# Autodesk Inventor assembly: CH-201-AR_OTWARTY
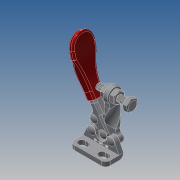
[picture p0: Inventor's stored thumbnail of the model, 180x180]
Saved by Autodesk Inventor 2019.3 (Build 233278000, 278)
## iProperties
Company: ·L?¤¤?
Created: 2010-06
Part Number: CH-201-AR_OTWARTY
Material: Ogólny
Description: STEP AP203
Document SubType Name: Assembly
Designer: CADENGINEERING4
Sending System: SolidWorks 2005179
Preprocessor: SwSTEP 2.0
Title: CH-201-AR.STEP
Author: ·L?¥Î?
Revision Number: ANY
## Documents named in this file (8)
- E:\STRONA\Horizontal toggle clamp\CH-201-AR\CH-201-AR_OTWARTY.iam
- E:\STRONA\Horizontal toggle clamp\CH-201-AR\201-AR-01___.ipt
- E:\STRONA\Horizontal toggle clamp\CH-201-AR\201-A-02___.ipt
- E:\STRONA\Horizontal toggle clamp\CH-201-AR\201-06___.ipt
- E:\STRONA\Horizontal toggle clamp\CH-201-AR\M4___.ipt
- E:\STRONA\Horizontal toggle clamp\CH-201-AR\201-03___.iam
- E:\STRONA\Horizontal toggle clamp\CH-201-AR\CH-SA-042007___.ipt
- E:\STRONA\Horizontal toggle clamp\CH-201-AR\201-A-04___.ipt
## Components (12 placed, 12 different names)
1. 201-AR-01_??_1 — Zestawiające:6, Zestawiające:7, Zestawiające:8, Zestawiające:16, Zestawiające:17, Zestawiające:20, Przejściowe:1
2. 201-A-02_??_2 — Zestawiające:1, Zestawiające:4, Zestawiające:5, Zestawiające:6, Zestawiające:22, Zestawiające:23
3. 201-06_??_3 — Zestawiające:7, Zestawiające:8, Zestawiające:22
4. 201-06_??_4 — Zestawiające:20, Zestawiające:21
5. M4_??_5 — Zestawiające:3, Zestawiające:5
6. M4_??_6 — Równoległe:1, Zestawiające:2, Zestawiające:4
7. 201-03_??_7 [sub-assembly] — Zestawiające:9, Zestawiające:10, Zestawiające:11, Zestawiające:12, Zestawiające:19, Przejściowe:1
8. 201-06_??_8 — Zestawiające:9, Zestawiające:12, Zestawiające:18
9. CH-SA-042007_??_9 — Równoległe:1, Zestawiające:1, Zestawiające:2, Zestawiające:3
10. 201-06_??_10 — Zestawiające:10, Zestawiające:11, Zestawiające:23
11. 201-A-04_??_11 — Zestawiające:13, Zestawiające:14, Zestawiające:15, Zestawiające:16, Zestawiające:18, Zestawiające:19, Zestawiające:21
12. 201-A-04_??_12 — Zestawiające:13, Zestawiające:14, Zestawiające:15, Zestawiające:17
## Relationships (25: Mate 23, Flush 1, Transitional 1)
- Równoległe:1 [Flush]: M4_??_6 ↔ CH-SA-042007_??_9
- Zestawiające:1 [Mate]: 201-A-02_??_2 ↔ CH-SA-042007_??_9
- Zestawiające:2 [Mate]: M4_??_6 ↔ CH-SA-042007_??_9
- Zestawiające:3 [Mate]: M4_??_5 ↔ CH-SA-042007_??_9
- Zestawiające:4 [Mate]: 201-A-02_??_2 ↔ M4_??_6
- Zestawiające:5 [Mate]: 201-A-02_??_2 ↔ M4_??_5
- Zestawiające:6 [Mate]: 201-AR-01_??_1 ↔ 201-A-02_??_2
- Zestawiające:7 [Mate]: 201-AR-01_??_1 ↔ 201-06_??_3
- Zestawiające:8 [Mate]: 201-AR-01_??_1 ↔ 201-06_??_3
- Zestawiające:9 [Mate]: 201-03_??_7 ↔ 201-06_??_8
- Zestawiające:10 [Mate]: 201-03_??_7 ↔ 201-06_??_10
- Zestawiające:11 [Mate]: 201-03_??_7 ↔ 201-06_??_10
- Zestawiające:12 [Mate]: 201-03_??_7 ↔ 201-06_??_8
- Zestawiające:13 [Mate]: 201-A-04_??_11 ↔ 201-A-04_??_12
- Zestawiające:14 [Mate]: 201-A-04_??_11 ↔ 201-A-04_??_12
- Zestawiające:15 [Mate]: 201-A-04_??_11 ↔ 201-A-04_??_12
- Zestawiające:16 [Mate]: 201-AR-01_??_1 ↔ 201-A-04_??_11
- Zestawiające:17 [Mate]: 201-AR-01_??_1 ↔ 201-A-04_??_12
- Zestawiające:18 [Mate]: 201-06_??_8 ↔ 201-A-04_??_11
- Zestawiające:19 [Mate]: 201-03_??_7 ↔ 201-A-04_??_11
- Zestawiające:20 [Mate]: 201-AR-01_??_1 ↔ 201-06_??_4
- Zestawiające:21 [Mate]: 201-06_??_4 ↔ 201-A-04_??_11
- Zestawiające:22 [Mate]: 201-A-02_??_2 ↔ 201-06_??_3
- Zestawiające:23 [Mate]: 201-A-02_??_2 ↔ 201-06_??_10
- Przejściowe:1 [Transitional]: 201-AR-01_??_1 ↔ 201-03_??_7
